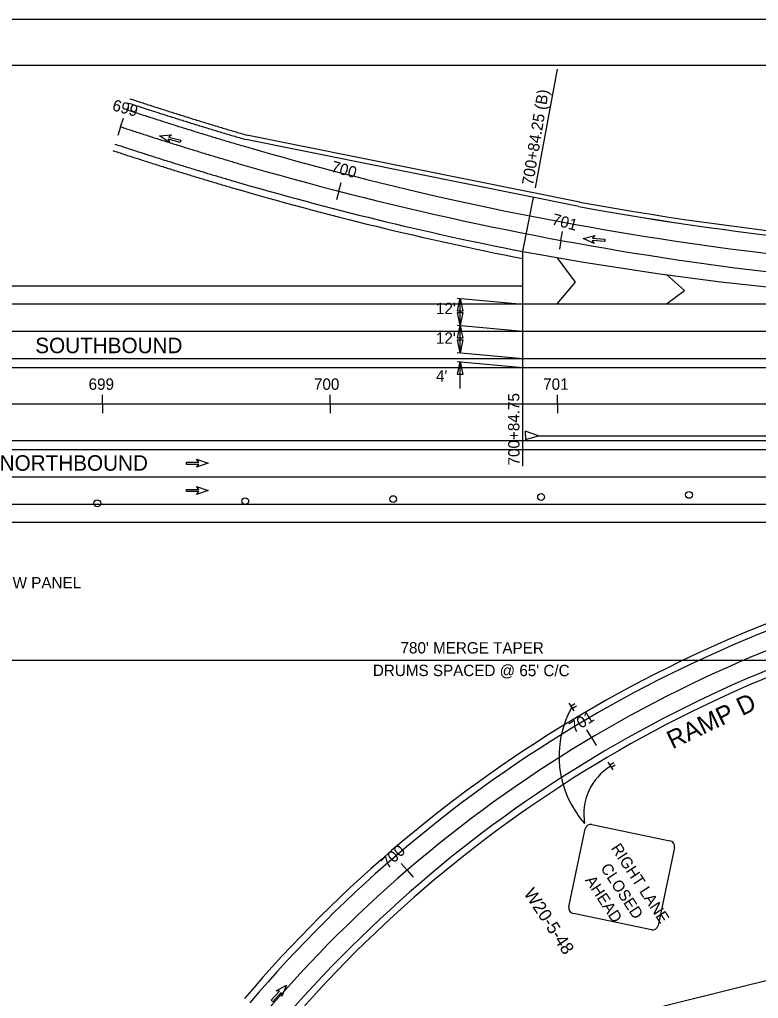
# Model space of a CAD drawing. Extents: x 0 to 1360, y 0 to 880.
# Drawn here: x 686.9 to 1011.5, y 449.6 to 880 of the extents above; entities that cross this region are included whole.
import ezdxf

# ---------------------------------------------------------------- set-up
doc = ezdxf.new("R2010")
doc.units = 0
for name, color, linetype in [('Default', 7, 'Continuous'), ('MT_P_Drums', 7, 'Continuous'), ('MT_P_Traffic_Attenuator', 7, 'Continuous'), ('PM_P_Cells', 7, 'Continuous'), ('PM_P_Channelizing_Line', 7, 'Continuous'), ('PM_P_Chevron_Line', 7, 'Continuous'), ('PM_P_Lane_Line', 7, 'Continuous'), ('PV_X_EOP', 7, 'Continuous'), ('PV_X_Shoulder', 7, 'Continuous'), ('RD_X_GR_Lt', 7, 'Continuous'), ('RD_X_GR_Rt', 7, 'Continuous'), ('RW_X_Fee_RW', 7, 'Continuous'), ('SH_Border', 7, 'Continuous'), ('SH_Cut_Line', 7, 'Continuous'), ('SH_Text', 7, 'Continuous'), ('SN_P_Signs', 7, 'Continuous'), ('SN_P_Text', 7, 'Continuous')]:
    doc.layers.add(name, color=color, linetype=linetype)

# ---------------------------------------------------------------- blocks, each defined once
blk = doc.blocks.new('SGN2PP')
at = {"layer": 'SN_P_Signs'}
for p, q in [((0, 0.024), (-0.08, 0.024)), ((0, 0.08), (0, -0.08)), ((0, 0), (0, 0)), ((0, 0), (0, 0)), ((0, -0.024), (-0.08, -0.024))]:
    blk.add_line(p, q, dxfattribs=at)
blk = doc.blocks.new('PMTHRP')
at = {"layer": 'PM_P_Cells'}
for p, q in [((-9.5, -0.5), (-9.5, 0.5)), ((-9.5, 0.5), (-4, 0.5)), ((-9.5, 0), (-9.5, 0)), ((-4, 0.5), (-5, 1.74)), ((-5, 1.74), (0, 0)), ((0, 0), (-5, -1.74)), ((0, 0), (0, 0)), ((-4, -0.5), (-9.5, -0.5)), ((-5, -1.74), (-4, -0.5))]:
    blk.add_line(p, q, dxfattribs=at)

msp = doc.modelspace()

# ---------------------------------------------------------------- linework, layer by layer
at = {"layer": 'Default'}
for p, q in [((913.5, 805.97), (923.16, 858.16)), ((731.25, 832.86), (732.5, 836.66)), ((731.25, 832.86), (730, 829.06)), ((827.14, 804.56), (828.14, 808.44)), ((827.14, 804.56), (826.14, 800.69)), ((908.05, 777.98), (912.72, 801.77)), ((924.76, 782.93), (925.48, 786.87)), ((924.76, 782.93), (924.03, 779)), ((879.2, 757.58), (908.03, 754.89)), ((880.46, 745.55), (880.46, 757.46)), ((908.03, 726.99), (908.03, 754.89)), ((879.2, 745.67), (908.03, 742.99)), ((880.46, 733.55), (880.46, 745.55)), ((879.2, 733.67), (908.03, 730.99)), ((879.2, 729.67), (908.03, 726.99)), ((880.46, 717.76), (880.46, 729.55)), ((195.52, 726.99), (1186.03, 726.99)), ((908.03, 683.62), (908.03, 726.99)), ((723.28, 710.99), (723.28, 714.99)), ((823.28, 710.99), (823.28, 714.99)), ((923.28, 710.99), (923.28, 714.99)), ((123.28, 710.99), (1223.28, 710.99)), ((723.28, 710.99), (723.28, 706.99)), ((823.28, 710.99), (823.28, 706.99)), ((923.28, 710.99), (923.28, 706.99)), ((203.21, 694.99), (1186.03, 694.99)), ((414.47, 658.99), (1153.28, 658.99)), ((590.97, 598.29), (1223.28, 598.29)), ((938.22, 564.31), (936.18, 567.75)), ((938.22, 564.31), (940.26, 560.87)), ((857.15, 505.98), (854.54, 509.01)), ((857.15, 505.98), (859.76, 502.95))]:
    msp.add_line(p, q, dxfattribs=at)
for points in [[(881.58, 751.86), (879.34, 751.86), (880.46, 757.46)], [(879.34, 751.15), (881.58, 751.15), (880.46, 745.55)], [(881.58, 739.95), (879.34, 739.95), (880.46, 745.55)], [(879.34, 739.15), (881.58, 739.15), (880.46, 733.55)], [(881.58, 723.95), (879.34, 723.95), (880.46, 729.55)]]:
    msp.add_lwpolyline(points, close=True, dxfattribs=at)
for centre, radius, start, end in [((1185.65, 2191.37), 1432.39, 253.66659, 269.99992), ((1185.65, 2191.37), 1416.39, 259.70806, 268.87075), ((1231.01, 71.81), 583.96, 101.43212, 139.68336), ((1231.01, 71.81), 572.96, 101.4321, 139.6834), ((1231.01, 71.81), 561.96, 101.4444, 139.6834), ((968.5, 556.1), 44.6, 151.0028, 221.6125), ((959.58, 530.69), 24.79, 121.747, 189.776)]:
    msp.add_arc(centre, radius, start, end, dxfattribs=at)
msp.add_spline([(731.25, 832.86), (733.79, 832.03), (736.35, 831.19), (738.93, 830.36), (741.5, 829.53), (744.07, 828.7), (746.64, 827.87), (749.22, 827.05), (751.8, 826.24), (754.37, 825.43), (756.95, 824.62), (759.53, 823.82), (762.12, 823.02), (764.7, 822.22), (767.28, 821.43), (769.87, 820.65), (772.46, 819.86), (775.04, 819.09), (777.64, 818.32), (780.23, 817.55), (782.82, 816.79)], degree=3, dxfattribs=at)
at = {"layer": 'MT_P_Drums'}
for centre in [(916.02, 670.09), (981.01, 671.01), (721.04, 667.34), (786.03, 668.26), (851.03, 669.17)]:
    msp.add_circle(centre, 1.5, dxfattribs=at)
at = {"layer": 'PM_P_Channelizing_Line'}
msp.add_line((908.05, 754.99), (1123.08, 754.99), dxfattribs=at)
msp.add_arc((1167.36, 2180.34), 1426.04, 259.52364, 268.22055, dxfattribs=at)
at = {"layer": 'PM_P_Chevron_Line'}
for points in [[(923.08, 754.99), (931.08, 764.5), (923.08, 775.38)], [(971.08, 754.99), (979.08, 760.89), (971.08, 767.87)]]:
    msp.add_lwpolyline(points, dxfattribs=at)
at = {"layer": 'PM_P_Lane_Line'}
for p, q in [((123.28, 742.99), (1223.28, 742.99)), ((123.28, 678.99), (1223.28, 678.99))]:
    msp.add_line(p, q, dxfattribs=at)
at = {"layer": 'PV_X_EOP'}
for p, q in [((908.05, 774.92), (908.05, 777.98)), ((908.05, 754.99), (908.05, 762.99)), ((123.28, 754.99), (908.05, 754.99)), ((123.28, 730.99), (1223.28, 730.99)), ((123.28, 690.99), (1223.28, 690.99)), ((239.97, 666.99), (1153.28, 666.99))]:
    msp.add_line(p, q, dxfattribs=at)
for centre, radius, start, end in [((1185.65, 2191.37), 1424.39, 253.66659, 269.76797), ((1185.65, 2191.37), 1440.39, 253.66659, 258.88811), ((1231.01, 71.81), 580.96, 101.43212, 139.68336), ((1231.01, 71.81), 564.96, 101.4321, 139.6834)]:
    msp.add_arc(centre, radius, start, end, dxfattribs=at)
for points in [[(733.75, 840.46), (736.27, 839.63), (738.83, 838.8), (741.39, 837.97), (743.95, 837.14), (746.51, 836.32), (749.08, 835.5), (751.64, 834.68), (754.2, 833.87), (756.77, 833.06), (759.34, 832.26), (761.91, 831.46), (764.47, 830.66), (767.04, 829.87), (769.62, 829.08), (772.19, 828.3), (774.76, 827.52), (777.34, 826.75), (779.91, 825.98), (782.49, 825.22), (785.08, 824.46)], [(728.75, 825.26), (731.3, 824.43), (733.88, 823.59), (736.46, 822.75), (739.04, 821.91), (741.63, 821.08), (744.21, 820.25), (746.8, 819.43), (749.39, 818.61), (751.98, 817.79), (754.57, 816.98), (757.16, 816.18), (759.76, 815.37), (762.35, 814.57), (764.95, 813.78), (767.55, 812.99), (770.15, 812.2), (772.75, 811.42), (775.36, 810.65), (777.96, 809.87), (780.56, 809.11)]]:
    msp.add_spline(points, degree=3, dxfattribs=at)
at = {"layer": 'PV_X_Shoulder'}
for p, q in [((932.59, 797.77), (786.28, 827.27)), ((908.05, 762.99), (908.05, 774.92)), ((188.69, 762.99), (908.05, 762.99)), ((195.52, 726.99), (1186.03, 726.99)), ((203.21, 694.99), (1186.03, 694.99)), ((414.47, 658.99), (1153.28, 658.99))]:
    msp.add_line(p, q, dxfattribs=at)
for centre, radius, start, end in [((1185.65, 2191.37), 1443.39, 253.66659, 258.9115), ((1185.65, 2191.37), 1416.39, 259.70798, 268.87075), ((1231.01, 71.81), 583.96, 101.43212, 139.68336), ((1231.01, 71.81), 561.96, 101.4444, 139.6834)]:
    msp.add_arc(centre, radius, start, end, dxfattribs=at)
for points in [[(734.69, 843.31), (737.21, 842.49), (739.76, 841.65), (742.32, 840.82), (744.87, 839.99), (747.43, 839.17), (749.99, 838.35), (752.55, 837.54), (755.11, 836.73), (757.67, 835.92), (760.23, 835.12), (762.79, 834.32), (765.36, 833.53), (767.92, 832.74), (770.49, 831.95), (773.06, 831.17), (775.63, 830.4), (778.2, 829.63), (780.77, 828.86), (783.34, 828.1), (786.28, 827.27)], [(727.81, 822.41), (730.36, 821.58), (732.95, 820.73), (735.53, 819.89), (738.12, 819.06), (740.71, 818.22), (743.3, 817.4), (745.89, 816.57), (748.48, 815.75), (751.08, 814.93), (753.67, 814.12), (756.27, 813.31), (758.87, 812.51), (761.47, 811.71), (764.08, 810.91), (766.68, 810.12), (769.29, 809.33), (771.89, 808.55), (774.5, 807.77), (777.11, 807), (779.72, 806.23)]]:
    msp.add_spline(points, degree=3, dxfattribs=at)
at = {"layer": 'RD_X_GR_Lt'}
for p, q in [((914.82, 696.99), (909, 699.04)), ((909, 699.04), (909.21, 695.31)), ((909.21, 695.31), (914.82, 696.99)), ((914.82, 696.99), (1210.03, 696.99))]:
    msp.add_line(p, q, dxfattribs=at)
msp.add_arc((1185.65, 2191.37), 1414.39, 259.70806, 269.76797, dxfattribs=at)
msp.add_spline([(735.31, 845.21), (737.83, 844.39), (740.38, 843.55), (742.93, 842.72), (745.49, 841.9), (748.04, 841.08), (750.6, 840.26), (753.15, 839.44), (755.71, 838.64), (758.27, 837.83), (760.83, 837.03), (763.39, 836.23), (765.95, 835.44), (768.51, 834.65), (771.07, 833.87), (773.64, 833.09), (776.2, 832.31), (778.77, 831.54), (781.34, 830.78), (783.9, 830.02), (786.82, 829.19)], degree=3, dxfattribs=at)
at = {"layer": 'RD_X_GR_Rt'}
msp.add_line((932.98, 799.73), (786.67, 829.23), dxfattribs=at)
at = {"layer": 'RW_X_Fee_RW'}
msp.add_line((948.28, 440.99), (1223.28, 509.49), dxfattribs=at)
at = {"layer": 'SH_Border'}
msp.add_lwpolyline([(60, 860), (1340, 860), (1340, 20), (60, 20)], close=True, dxfattribs=at)
at = {"layer": 'SH_Cut_Line'}
msp.add_lwpolyline([(0, 0), (1360, 0), (1360, 880), (0, 880)], close=True, dxfattribs=at)
at = {"layer": 'SN_P_Signs'}
for points in [[(938.36, 526.09), (972.62, 518.95)], [(928.26, 489.89), (935.4, 524.16)], [(974.56, 516), (967.42, 481.73)], [(964.46, 479.8), (930.2, 486.93)]]:
    msp.add_lwpolyline(points, dxfattribs=at)
for centre, start, end in [((937.85, 523.65), 78.2302, 168.2302), ((972.11, 516.51), 348.2302, 78.2302), ((930.71, 489.38), 168.2302, 258.2302), ((964.97, 482.24), 258.2302, 348.2302)]:
    msp.add_arc(centre, 2.5, start, end, dxfattribs=at)

# ---------------------------------------------------------------- block references
at = {"layer": 'MT_P_Traffic_Attenuator', "xscale": 25, "yscale": 24.999999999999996, "rotation": -147.45207414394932}
for p in [(929.49, 577.72), (946.54, 551.77)]:
    msp.add_blockref('SGN2PP', p, dxfattribs=at)
at = {"layer": 'SH_Text'}
for p, rotation in [((748.41, 828.93), 164.85798466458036), ((934.54, 783.77), 174.6620262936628), ((804.23, 455.48), 47.04069910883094)]:
    msp.add_blockref('PMTHRP', p, dxfattribs=dict(at, rotation=rotation))
for p in [(769.67, 684.94), (769.67, 672.95)]:
    msp.add_blockref('PMTHRP', p, dxfattribs=at)

# ---------------------------------------------------------------- texts
at = {"layer": 'Default'}
for s, height, rotation, p in [('700+84.25 (B)', 5, 80.5093, (912.47, 806.88)), ('699', 5, 344.4839, (727.28, 840.19)), ('700', 5, 344.4839, (823.42, 813.2)), ('701', 5, 344.4839, (920.4, 790.05)), ('699', 5, 0, (717.22, 717.22)), ('700', 5, 0, (816.22, 717.22)), ('701', 5, 0, (916.92, 717.22)), ('RAMP D', 8, 25.5302, (973.72, 559.1)), ('701', 5, 32.0772, (930.39, 566.13)), ('700', 5, 42.9574, (848.58, 506.39))]:
    msp.add_text(s, height=height, rotation=rotation, dxfattribs=at).set_placement(p)
at = {"layer": 'SH_Text'}
for s, rotation, p in [("12'", 0, (869.83, 750.49)), ("12'", 0, (869.83, 737.47)), ("4'", 0, (869.83, 720.79)), ('700+84.75', 90.1851, (906.56, 683.99)), ('FLASHING ARROW PANEL', 0.1851, (629.23, 629.69)), ("780' MERGE TAPER", 359.9486, (854.26, 601.29)), ("DRUMS SPACED @ 65' C/C", 359.9486, (842.09, 591.37))]:
    msp.add_text(s, height=5, rotation=rotation, dxfattribs=at).set_placement(p)
for s, p in [('SOUTHBOUND', (693.78, 733.33)), ('NORTHBOUND', (678.11, 681.65))]:
    msp.add_text(s, height=6.8, dxfattribs=at).set_placement(p)
at = {"layer": 'SN_P_Signs'}
for s, p in [('RIGHT LANE', (946.53, 515.71)), ('CLOSED', (941.94, 507)), ('AHEAD', (935.17, 501.62))]:
    msp.add_text(s, height=5, rotation=303.2302, dxfattribs=at).set_placement(p)
at = {"layer": 'SN_P_Text'}
msp.add_text('W20-5-48', height=5.6, rotation=303.2302, dxfattribs=at).set_placement((908.17, 495.86))

doc.saveas('drawing.dxf')
